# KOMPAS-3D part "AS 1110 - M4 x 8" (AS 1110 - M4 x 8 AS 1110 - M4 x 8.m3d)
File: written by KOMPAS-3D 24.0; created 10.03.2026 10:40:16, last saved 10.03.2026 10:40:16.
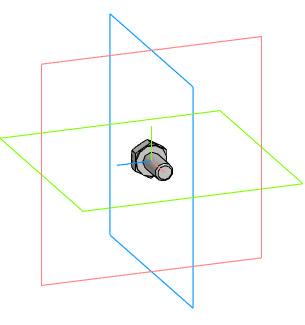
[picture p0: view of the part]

Document properties: Автор: R2D2; Полное имя файла: C:\Users\R2D2\Downloads\AS 1110 - M4 x 8 AS 1110 - M4 x 8.m3d

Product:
- Body: Solid1  | qty 1
- Part/product: AS 1110 - M4 x 8
    Комментарий: Болты и винты   шестигранные точные   метрические ISO
    additional columns: Сталь, мягкая

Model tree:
1. Solid1  (labels: Solid1)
